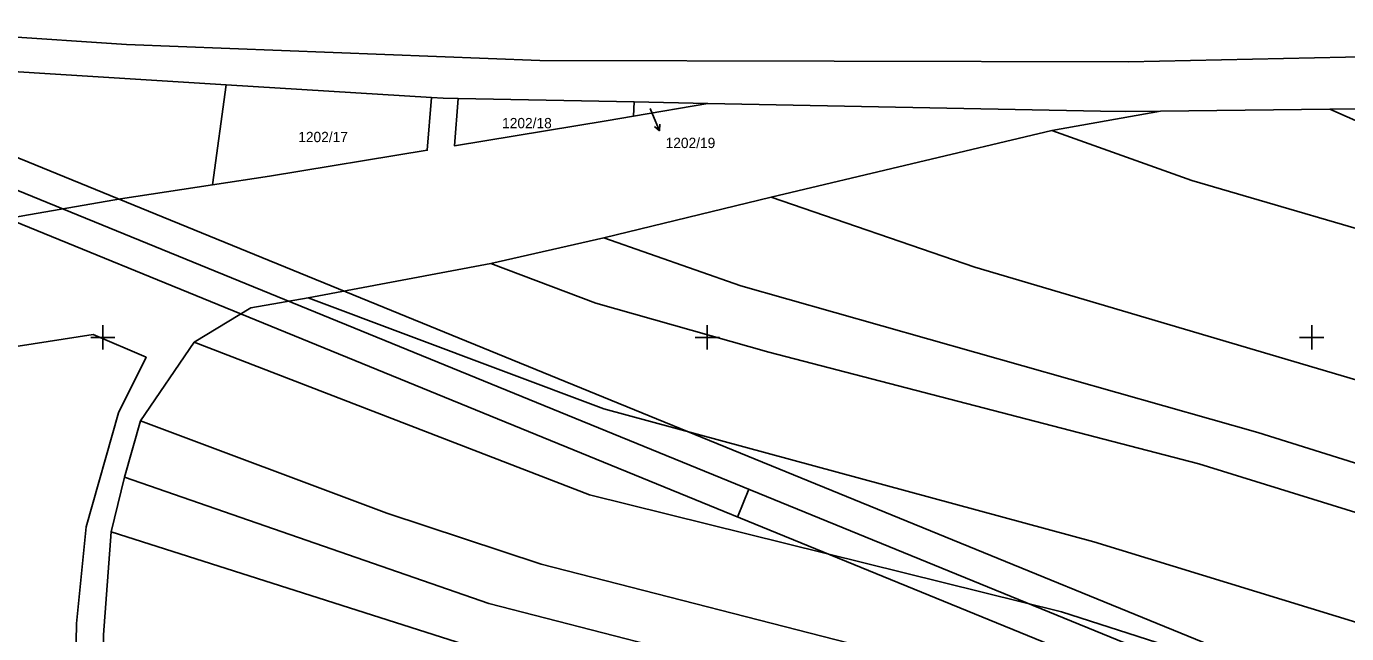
# Model space of a CAD drawing. Extents: x -779302 to -774398, y -1144902 to -1142831.
# Drawn here: x -776612.7 to -776394.2, y -1143949 to -1143848.6 of the extents above; entities that cross this region are included whole.
import ezdxf

# ---------------------------------------------------------------- set-up
doc = ezdxf.new("R2010")
doc.units = 0
for name, color, linetype in [('hektosit - Vrstva 5', 7, 'Continuous'), ('Hranice parcel', 7, 'Continuous'), ('Parcelní čísla', 7, 'Continuous'), ('Pop  PČ popisy', 7, 'Continuous'), ('Vnitřní kresba', 7, 'Continuous'), ('Vrstva 1', 7, 'Continuous')]:
    doc.layers.add(name, color=color, linetype=linetype)

msp = doc.modelspace()

# ---------------------------------------------------------------- linework, layer by layer
at = {"layer": 'hektosit - Vrstva 5'}
for p, q in [((-776600, -1143898), (-776600, -1143902)), ((-776500, -1143898), (-776500, -1143902)), ((-776400, -1143898), (-776400, -1143902)), ((-776602, -1143900), (-776598, -1143900)), ((-776502, -1143900), (-776498, -1143900)), ((-776402, -1143900), (-776398, -1143900))]:
    msp.add_line(p, q, dxfattribs=at)
at = {"layer": 'Hranice parcel'}
for p, q in [((-776581.88, -1143874.76), (-776579.58, -1143858.21)), ((-776579.58, -1143858.21), (-776545.63, -1143860.33)), ((-776541.24, -1143860.5), (-776512.12, -1143861.06)), ((-776512.23, -1143863.4), (-776512.12, -1143861.06)), ((-776499.94, -1143861.3), (-776512.23, -1143863.4)), ((-776512.12, -1143861.06), (-776499.94, -1143861.3)), ((-776443.01, -1143865.77), (-776425.04, -1143862.58)), ((-776425.04, -1143862.58), (-776396.99, -1143862.27)), ((-776443.01, -1143865.77), (-776489.41, -1143876.78)), ((-776419.82, -1143874.06), (-776443.01, -1143865.77)), ((-776517.13, -1143883.53), (-776489.41, -1143876.78)), ((-776535.81, -1143887.79), (-776517.13, -1143883.53)), ((-776566.02, -1143893.46), (-776535.81, -1143887.79)), ((-776593.79, -1143913.81), (-776584.9, -1143900.82)), ((-776596.43, -1143923.1), (-776593.79, -1143913.81)), ((-776598.61, -1143932.15), (-776596.43, -1143923.1))]:
    msp.add_line(p, q, dxfattribs=at)
for points in [[(-776643.49, -1143854.22), (-776610.51, -1143856.28), (-776579.58, -1143858.21)], [(-776545.63, -1143860.33), (-776546.34, -1143869.04), (-776572.45, -1143873.34), (-776581.88, -1143874.76)], [(-776545.63, -1143860.33), (-776543.68, -1143860.45), (-776541.24, -1143860.5)], [(-776512.23, -1143863.4), (-776516.72, -1143864.17), (-776541.84, -1143868.3), (-776541.24, -1143860.5)], [(-776499.94, -1143861.3), (-776434.96, -1143862.56), (-776430.74, -1143862.64), (-776425.04, -1143862.58)], [(-776396.99, -1143862.27), (-776328.8, -1143861.5), (-776317.92, -1143860.64)], [(-776152.51, -1143971.59), (-776341.75, -1143886.7), (-776396.99, -1143862.27)], [(-776581.88, -1143874.76), (-776597.08, -1143877.06), (-776613.22, -1143879.92), (-776616.82, -1143880.56), (-776633.03, -1143882.33), (-776646.96, -1143884.19)], [(-776147.38, -1143985.8), (-776159.54, -1143981.75), (-776219.35, -1143953.95), (-776270.48, -1143930.82), (-776320.26, -1143907.26), (-776342.91, -1143898.29), (-776380.21, -1143885.62), (-776419.82, -1143874.06)], [(-776489.41, -1143876.78), (-776455.73, -1143888.41), (-776360.45, -1143916.55)], [(-776130.8, -1144031.65), (-776167.18, -1144019.46), (-776296.05, -1143958.5), (-776332.97, -1143941.86), (-776361.98, -1143930.46), (-776408.9, -1143915.72), (-776494.43, -1143891.48), (-776517.13, -1143883.53)], [(-776127.12, -1144041.75), (-776162.43, -1144029.85), (-776192.7, -1144017.69), (-776241.68, -1143994.5), (-776321.54, -1143955.7), (-776383.3, -1143931.9), (-776418.7, -1143920.93), (-776489.84, -1143902.44), (-776518.46, -1143894.36), (-776535.81, -1143887.79)], [(-776584.9, -1143900.82), (-776575.51, -1143895.09), (-776566.02, -1143893.46)], [(-776119.18, -1144063.71), (-776170, -1144046.22), (-776237.87, -1144019.26), (-776326.2, -1143972.4), (-776378, -1143951.65), (-776436.08, -1143933.84), (-776517.12, -1143911.82), (-776566.02, -1143893.46)], [(-776820, -1143895.49), (-776772.87, -1143897.45), (-776747.85, -1143898.96), (-776698.05, -1143910.34), (-776694.83, -1143910.84), (-776657.28, -1143908.19), (-776601.62, -1143899.55), (-776592.84, -1143903.3), (-776597.4, -1143912.49), (-776602.75, -1143931.33), (-776604.39, -1143947.31), (-776605.13, -1143989.13)], [(-776111.68, -1144084.62), (-776181.26, -1144059.74), (-776246.74, -1144031.99), (-776297.59, -1144005.18), (-776341.39, -1143983.08), (-776381.58, -1143964.67), (-776441.43, -1143945.4), (-776519.5, -1143926.07), (-776584.9, -1143900.82)], [(-776593.79, -1143913.81), (-776553, -1143929.07), (-776527.51, -1143937.51), (-776470.29, -1143952.19), (-776437.66, -1143960.66), (-776390.42, -1143976.01), (-776344.1, -1143996.17), (-776221.27, -1144057.17), (-776180.2, -1144074), (-776142.2, -1144086.85), (-776107.01, -1144097.64)], [(-776103.17, -1144108.34), (-776139.62, -1144097.29), (-776185.19, -1144082.67), (-776230.28, -1144063.14), (-776268.85, -1144045.98), (-776311.69, -1144022.93), (-776347.15, -1144004.12), (-776382.3, -1143988.84), (-776427.82, -1143973.66), (-776507.88, -1143951.31), (-776536.14, -1143944), (-776596.43, -1143923.1)], [(-776598.61, -1143932.15), (-776599.89, -1143949.22), (-776600.02, -1143957.46)], [(-776098.85, -1144120.12), (-776143.82, -1144104.66), (-776186.51, -1144088.97), (-776252.37, -1144061.74), (-776287.1, -1144045.07), (-776351.09, -1144013.34), (-776382, -1143998.69), (-776410.54, -1143987.67), (-776454.04, -1143974.87), (-776495.11, -1143963.98), (-776524.93, -1143955.67), (-776598.61, -1143932.15)]]:
    msp.add_lwpolyline(points, dxfattribs=at)
at = {"layer": 'Pop  PČ popisy'}
for p, q in [((-776509.48, -1143862.13), (-776509.07, -1143863.09)), ((-776509.07, -1143863.09), (-776507.9, -1143865.85)), ((-776507.9, -1143865.85), (-776508.75, -1143865.13)), ((-776507.9, -1143865.85), (-776507.83, -1143864.74))]:
    msp.add_line(p, q, dxfattribs=at)
at = {"layer": 'Vnitřní kresba'}
for p, q in [((-776694.77, -1143844.97), (-776596.12, -1143851.55)), ((-776596.12, -1143851.55), (-776527.73, -1143854.17)), ((-776285.88, -1143851.28), (-776430.3, -1143854.43)), ((-776430.3, -1143854.43), (-776527.73, -1143854.17))]:
    msp.add_line(p, q, dxfattribs=at)
at = {"layer": 'Vrstva 1'}
msp.add_line((-776495, -1143929.73), (-776493.11, -1143925.11), dxfattribs=at)
for points in [[(-775713.68, -1144238.31), (-776879.99, -1143761.57), (-776992.36, -1144036.48), (-775826.05, -1144513.22)], [(-775828.78, -1144506.7), (-776985.84, -1144033.74), (-776877.25, -1143768.09), (-775720.2, -1144241.05)], [(-775726.71, -1144243.78), (-776684.76, -1143852.17), (-776789.57, -1144108.58), (-775831.52, -1144500.19)], [(-775831.52, -1144500.19), (-776789.57, -1144108.58), (-776684.76, -1143852.17), (-775726.71, -1144243.78)]]:
    msp.add_lwpolyline(points, close=True, dxfattribs=at)

# ---------------------------------------------------------------- texts
at = {"layer": 'Parcelní čísla'}
for s, p in [('1202/18', (-776533.95, -1143865.4)), ('1202/17', (-776567.68, -1143867.7)), ('1202/19', (-776506.9, -1143868.68))]:
    msp.add_text(s, height=1.7, dxfattribs=at).set_placement(p)

doc.saveas('drawing.dxf')
